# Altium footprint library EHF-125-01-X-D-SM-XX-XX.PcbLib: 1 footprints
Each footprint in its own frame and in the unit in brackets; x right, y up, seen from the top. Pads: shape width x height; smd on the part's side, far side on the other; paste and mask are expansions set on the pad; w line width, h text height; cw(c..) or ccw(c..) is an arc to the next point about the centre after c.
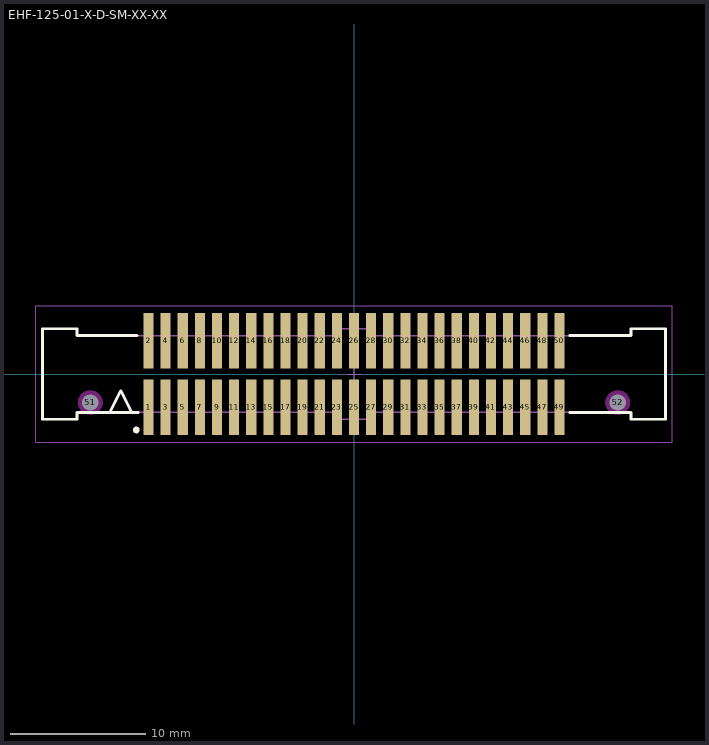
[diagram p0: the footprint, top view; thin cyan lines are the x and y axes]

## EHF-125-01-X-D-SM-XX-XX [mm] "1.27mm pitch, 50 pin, ejector header"
height 8.51
pads (52):
  rect 0.75x4.1 smd mask+0: 1(-15.24,-2.475) 2(-15.24,2.475) 3(-13.97,-2.475) 4(-13.97,2.475) 5(-12.7,-2.475) 6(-12.7,2.475) 7(-11.43,-2.475) 8(-11.43,2.475) 9(-10.16,-2.475) 10(-10.16,2.475) 11(-8.89,-2.475) 12(-8.89,2.475) 13(-7.62,-2.475) 14(-7.62,2.475) 15(-6.35,-2.475) 16(-6.35,2.475) 17(-5.08,-2.475) 18(-5.08,2.475) 19(-3.81,-2.475) 20(-3.81,2.475) 21(-2.54,-2.475) 22(-2.54,2.475) 23(-1.27,-2.475) 24(-1.27,2.475) 25(0,-2.475) 26(0,2.475) 27(1.27,-2.475) 28(1.27,2.475) 29(2.54,-2.475) 30(2.54,2.475) 31(3.81,-2.475) 32(3.81,2.475) 33(5.08,-2.475) 34(5.08,2.475) 35(6.35,-2.475) 36(6.35,2.475) 37(7.62,-2.475) 38(7.62,2.475) 39(8.89,-2.475) 40(8.89,2.475) 41(10.16,-2.475) 42(10.16,2.475) 43(11.43,-2.475) 44(11.43,2.475) 45(12.7,-2.475) 46(12.7,2.475) 47(13.97,-2.475) 48(13.97,2.475) 49(15.24,-2.475) 50(15.24,2.475)
  round 1 hole 1.2 unplated mask+0: 51(-19.56,-2.11) 52(19.56,-2.11)
Top Overlay:
  circle w0.25: c-16.15,-4.15 r0.125
  lines w0.2: -18.1,-2.85 -17.3,-1.25 -16.5,-2.85 ; -16.1,2.85 -20.55,2.85 -20.55,3.35 -23.1,3.35 -23.1,-3.35 -20.55,-3.35 -20.55,-2.85 -16,-2.85 ; 16,-2.85 20.55,-2.85 20.55,-3.35 23.1,-3.35 23.1,3.35 20.55,3.35 20.55,2.85 16,2.85
Keep-Out Layer:
  pour cut-out: -18.652,-2.11 -18.683,-1.875 -18.774,-1.656 -18.918,-1.468 -19.106,-1.324 -19.325,-1.233 -19.56,-1.202 -19.795,-1.233 -20.014,-1.324 -20.202,-1.468 -20.346,-1.656 -20.437,-1.875 -20.468,-2.11 -20.437,-2.345 -20.346,-2.564 -20.202,-2.752 -20.014,-2.896 -19.795,-2.987 -19.56,-3.018 -19.325,-2.987 -19.106,-2.896 -18.918,-2.752 -18.774,-2.564 -18.683,-2.345
  pour cut-out: 20.468,-2.11 20.437,-1.875 20.346,-1.656 20.202,-1.468 20.014,-1.324 19.795,-1.233 19.56,-1.202 19.325,-1.233 19.106,-1.324 18.918,-1.468 18.774,-1.656 18.683,-1.875 18.652,-2.11 18.683,-2.345 18.774,-2.564 18.918,-2.752 19.106,-2.896 19.325,-2.987 19.56,-3.018 19.795,-2.987 20.014,-2.896 20.202,-2.752 20.346,-2.564 20.437,-2.345
Mechanical 12:
  lines w0.001: -23.1,-3.35 -20.55,-3.35 -20.55,-2.85 -1.25,-2.85 -1.25,-3.35 1.25,-3.35 1.25,-2.85 20.55,-2.85 20.55,-3.35 23.1,-3.35 23.1,3.35 20.55,3.35 20.55,2.85 1.25,2.85 1.25,3.35 -1.25,3.35 -1.25,2.85 -20.55,2.85 -20.55,3.35 -23.1,3.35 -23.1,-3.35
Mechanical 13:
  lines w0.1: -18.1,-2.85 -17.3,-1.25 -16.5,-2.85 ; -23.1,-3.35 -20.55,-3.35 -20.55,-2.85 -1.25,-2.85 -1.25,-3.35 1.25,-3.35 1.25,-2.85 20.55,-2.85 20.55,-3.35 23.1,-3.35 23.1,3.35 20.55,3.35 20.55,2.85 1.25,2.85 1.25,3.35 -1.25,3.35 -1.25,2.85 -20.55,2.85 -20.55,3.35 -23.1,3.35 -23.1,-3.35
  text ".Designator" at 0.254,0.254 h1.52
Mechanical 15:
  lines w0.05: -0.5,0 0.5,0 ; 0,-0.5 0,0.5 ; -23.6,-5.05 23.6,-5.05 23.6,5.05 -23.6,5.05 -23.6,-5.05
